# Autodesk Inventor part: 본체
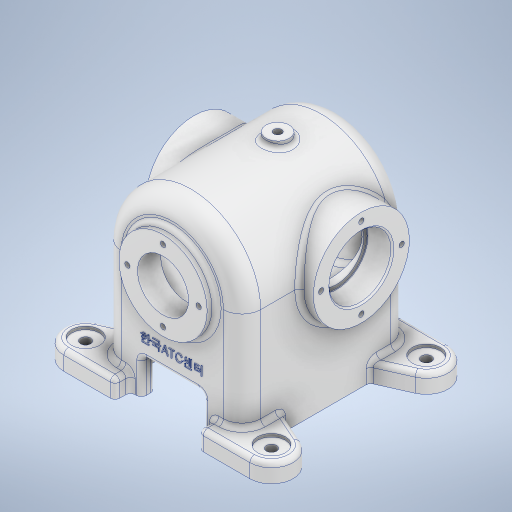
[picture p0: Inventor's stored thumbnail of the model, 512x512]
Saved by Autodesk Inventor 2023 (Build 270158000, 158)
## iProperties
Created: 2024-09
Part Number: 본체
Material: 알루미늄 6061
Document SubType Name: Modeling
Designer: asung
Density: 2.7 g/cm^3
Appearance: 알루미늄 - 평지
Mass: 1342.63 g
Surface Area: 1154.13 cm^2
Volume: 497.272 cm^3
Author: asung
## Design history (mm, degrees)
sketch "스케치4"
  geometry: L1 (-45, 0)-(-45, -76); L2 (45, 0)-(45, -76); L3 (0, 0)-(0, -76); L4 (0, -76)-(20, -76); L5 (0, -76)-(-20, -76); L6 (20, -76)-(20, -53); L7 (45, -76)-(20, -76); L8 (-45, -76)-(-20, -76); L9 (-20, -76)-(-20, -53); L10 (-20, -53)-(20, -53); A1 r 45 centre (0, 0) between (-45, 0) and (45, 0); 1 further point
  constraints: 20 end point, 4 vertical, 2 horizontal, 2 point on circle, 1 centre point, 1 coincident, 1 collinear, 1 perpendicular, 1 point on line, 1 tangent
  dimensions: "d14" = 90 diameter of A1; "d15" = 76 distance of L1.start L1.end; "d16" = 76 distance of L2.start L2.end; "d17" = 20 distance of L3.end L4.end; "d18" = 20 distance of L3.end L5.end; "d19" = 23 distance of L4.end L6.end; "d20" = 23 distance of L5.end L9.end
extrude "돌출4" new body sketch "스케치4" distance "d21" = 108; taper "d22" = 0 deg
feature "쉘2" dims "d23" = 9
sketch "스케치5"
  geometry: C1 r 45 at (0, 0); 1 further point
  constraints: 1 centre point, 1 coincident
  dimensions: "d24" = 90 diameter of C1
extrude "돌출5" join sketch "스케치5" distance "d25" = 108; taper "d26" = 0 deg
node "작업 평면1"
sketch "스케치6"
  geometry: C1 r 28.5 at (0, 0); 1 further point
  constraints: 1 centre point, 1 coincident
  dimensions: "d28" = 57 diameter of C1
extrude "돌출6" join sketch "스케치6" distance "d29" = 6; taper "d30" = 0 deg
fillet "모깎기1" dims "d31" = 12
sketch "스케치7"
  geometry: L1 (28.5, 6)-(-28.5, 6) reference; C1 r 31 at (0, -68); 1 further point
  constraints: 1 centre point, 1 vertical alignment
  dimensions: "d32" = 62 diameter of C1; "d33" = 74 distance from line of C1.centre L1
extrude "돌출7" join sketch "스케치7" stored distance "d34" = 6; taper "d35" = 0 deg
sketch "스케치8"
  geometry: C1 r 31 at (0, 0) reference; 2 further points
  constraints: 1 coincident
hole "구멍1" sketch "스케치8" at (0, 0) diameter "d36" = 35; stored, may be unused: countersink angle "d40" = 90 deg, drill point angle "d42" = 118 deg; dims "d37" = 119, "d38" = 40, "d39" = 16, "d41" = 120
sketch "스케치9"
  geometry: C1 r 31 at (0, 0) reference; 2 further points
  constraints: 1 coincident
hole "구멍2" sketch "스케치9" at (0, 0) diameter "d43" = 35; stored, may be unused: countersink angle "d47" = 90 deg, drill point angle "d49" = 118 deg; dims "d44" = 6, "d45" = 40, "d46" = 16, "d48" = 120
node "작업 평면2"
sketch "스케치10"
  geometry: C1 r 37 at (0, 0); 1 further point
  constraints: 1 centre point, 1 coincident
  dimensions: "d51" = 74 diameter of C1
extrude "돌출8" cut sketch "스케치10" distance "d52" = 90; taper "d53" = 0 deg
fillet "모깎기2" dims "d54" = 3
sketch "스케치11" dims "d55" = 52
  geometry: C1 r 20 at (0, 0) reference; C2 r 31 at (0, 0) reference; 3 further points
  constraints: 2 vertical alignment, 1 coincident, 2 other
hole "구멍3" sketch "스케치11" at (0, 26) diameter "d56" = 3.45873; stored, may be unused: countersink angle "d60" = 90 deg, drill point angle "d62" = 118 deg; dims "d57" = 8, "d58" = 40, "d59" = 16, "d61" = 10
sketch "스케치12"
  geometry: C1 r 28.5 at (0, 0) reference; 2 further points
  constraints: 1 coincident
hole "구멍4" sketch "스케치12" at (0, 0) diameter "d66" = 33; stored, may be unused: countersink angle "d70" = 90 deg, drill point angle "d72" = 118 deg; dims "d67" = 8, "d68" = 4, "d69" = 2, "d71" = 50
sketch "스케치13" dims "d74" = 46
  geometry: C1 r 28.5 at (0, 0); 3 further points
  constraints: 2 coincident, 2 vertical alignment, 1 centre point, 2 other
  dimensions: "d73" = 57 diameter of C1
hole "구멍5" sketch "스케치13" at (0, 23) diameter "d75" = 3.45873; stored, may be unused: countersink angle "d79" = 90 deg, drill point angle "d81" = 118 deg; dims "d76" = 8, "d77" = 4, "d78" = 2, "d80" = 10
fillet "모깎기3" dims "d85" = 3
fillet "모깎기4" dims "d86" = 0.3
chamfer "모따기1" distance "d87" = 1; stored, may be unused: second distance "d88" = 2, angle "d89" = 45 deg
node "작업 평면3"
sketch "스케치14"
  geometry: L1 (28.5, 6)-(-28.5, 6) reference; C1 r 7.5 at (0, -68); 1 further point
  constraints: 1 centre point, 1 vertical alignment
  dimensions: "d91" = 15 diameter of C1; "d92" = 74 distance from line of C1.centre L1
extrude "돌출9" join sketch "스케치14" stored distance "d93" = 90; taper "d94" = 0 deg
node "작업 평면4"
sketch "스케치15"
  geometry: L1 (28.5, 6)-(-28.5, 6) reference; C1 r 7.5 at (0, -68); 1 further point
  constraints: 1 centre point, 1 vertical alignment
  dimensions: "d96" = 15 diameter of C1; "d97" = 74 distance from line of C1.centre L1
extrude "돌출10" join sketch "스케치15" stored distance "d98" = 10; taper "d99" = 0 deg
sketch "스케치16"
  geometry: C1 r 7.5 at (0, 0) reference; 2 further points
  constraints: 1 coincident
hole "구멍6" sketch "스케치16" at (0, 0) diameter "d100" = 5.1881; stored, may be unused: countersink angle "d104" = 90 deg, drill point angle "d106" = 118 deg; dims "d101" = 199, "d102" = 4, "d103" = 2, "d105" = 200
fillet "모깎기5" dims "d107" = 3
sketch "스케치17"
  geometry: L1 (13, -99)-(-53, -99) reference; L2 (25, -3)-(25, -87) reference; L3 (40, -95)-(-80, -95); L4 (-80, -95)-(-80, 5); L5 (-80, 5)-(40, 5); L6 (40, 5)-(40, -95); L7 (40, -95)-(-80, 5); L8 (-80, -95)-(40, 5); L9 (-80, -109)-(-47, -109); L10 (-47, -109)-(-47, -95); L11 (-65, -3)-(-65, -87) reference; L12 (-65, -73)-(-85.693, -82.21); L13 (-40, -99)-(-53, -99) reference; L14 (-40, -90)-(-40, -99) reference; L15 (-40, -90)-(-56, -90) reference; L16 (-56, -90)-(-56, 0) reference; L17 (-56, 0)-(-40, 0) reference; L18 (-40, 9)-(-40, 0) reference; L19 (-53, 9)-(-40, 9) reference; L20 (-65, -3)-(-65, -87) reference; A1 r 14 centre (-80, -95) between (-80, -109) and (-85.693, -82.21); A2 r 12 centre (-53, -87) between (-65, -87) and (-53, -99) reference; A3 r 12 centre (-53, -3) between (-53, 9) and (-65, -3) reference; 7 further points
  constraints: 18 end point, 2 horizontal, 2 midpoint, 2 parallel, 2 perpendicular, 2 point on circle, 2 point on line, 2 tangent, 1 centre point, 1 coincident
  dimensions: "d111" = 120 distance of L4.end L5.end; "d112" = 100 distance of L3.end L4.end; "d113" = 15 distance between parallel lines of L2 L6; "d114" = 104 distance between parallel lines of L1 L5; "d115" = 14 radius of A1; "d116" = 18 distance between parallel lines of L11 L10; "d117" = 36 vertical distance of L12.start L9.start
extrude "돌출11" join sketch "스케치17" distance "d118" = 12; taper "d119" = 0 deg
node "작업 평면5"
fillet "모깎기6" dims "d120" = 3
fillet "모깎기7" dims "d121" = 3
fillet "모깎기8" dims "d122" = 3
sketch "스케치18"
  geometry: L1 (60, -76)-(30, -76) reference; 2 further points
  constraints: 1 vertical alignment, 1 other
  dimensions: "d123" = 35 distance from line of L1 point (0, -41)
feature "엠보싱1" sketch "스케치18" dims "d27" = 54, "d124" = 0.5, "d125" = 0
sketch "스케치19"
  geometry: A1 r 11 centre (-80, 95) between (-80, 106) and (-84.473, 84.95) reference; A2 r 11 centre (40, 95) between (44.473, 84.95) and (40, 106) reference; A3 r 11 centre (40, -5) between (40, -16) and (44.473, 5.05) reference; A4 r 11 centre (-80, -5) between (-84.473, 5.05) and (-80, -16) reference; 6 further points
  constraints: 4 coincident
hole "구멍7" sketch "스케치19" at (-80, 95), (40, 95), (40, -5), (-80, -5) diameter "d126" = 6.6; stored, may be unused: countersink angle "d130" = 90 deg, drill point angle "d132" = 118 deg; dims "d127" = 199, "d128" = 18, "d129" = 2, "d131" = 20
fillet "모깎기9" dims "d133" = 3
node "솔리드2"
mirror "미러1"
pattern_circular "원형 패턴1" dims angle "d64" = 360 deg
mirror "미러2"
pattern_circular "원형 패턴2" dims angle "d83" = 360 deg
mirror "미러3"
mirror "미러4"
node "투영된 루프2"
node "투영된 루프3"
feature "A9D066F2-1C7D-4E18-AEED-F7BC21143FA4" dims "d36" = 35, "d37" = 119, "d38" = 40, "d39" = 16, "d40" = 90 deg, "d41" = 120, "d42" = 118 deg
other parameters: "d50" = -9, "d90" = 49, "d95" = -98
